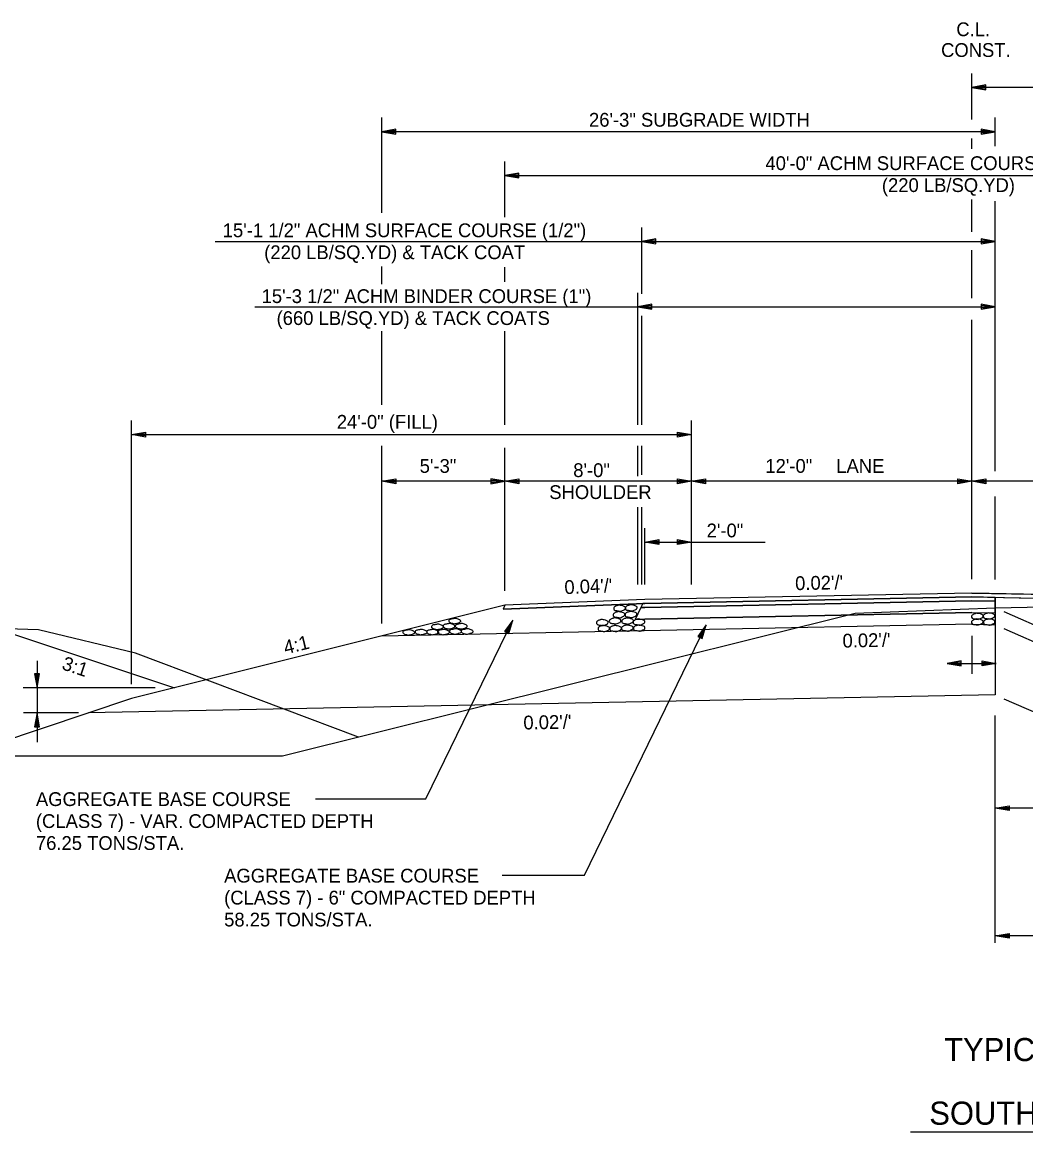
# Model space of a CAD drawing. Extents: x 1398565 to 1398920, y 1968324 to 1968581.
# Drawn here: x 1398600.91 to 1398643.9, y 1968376.33 to 1968423.84 of the extents above; entities that cross this region are included whole.
import ezdxf

# ---------------------------------------------------------------- set-up
doc = ezdxf.new("R2010")
doc.units = 0
for name, color, linetype in [('1', 7, 'Continuous'), ('10', 7, 'Continuous'), ('19', 7, 'Continuous'), ('42', 7, 'Continuous'), ('7', 7, 'Continuous'), ('Default', 7, 'Continuous'), ('Level 1', 7, 'Continuous')]:
    doc.layers.add(name, color=color, linetype=linetype)

# ---------------------------------------------------------------- blocks, each defined once
blk = doc.blocks.new('ROCKS')
at = {"layer": '1'}
blk.add_spline([(0.013, 0.06), (0.053, 0.053), (0.107, 0.033), (0.133, 0.013), (0.133, -0.007), (0.12, -0.033), (0.107, -0.04), (0.073, -0.053), (0.033, -0.067), (0.013, -0.067), (-0.02, -0.06), (-0.06, -0.053), (-0.087, -0.047), (-0.113, -0.02), (-0.113, -0.007), (-0.107, 0.02), (-0.087, 0.033), (-0.067, 0.047), (-0.033, 0.053), (-0.02, 0.06), (0.013, 0.06)], degree=3, dxfattribs=at)
blk = doc.blocks.new('4TO1 ABC')
at = {"layer": '1', "xscale": 0.1312491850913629, "yscale": 0.1312491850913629, "rotation": 180}
for p in [(0.00175, -0.00875), (-0.03325, -0.0385), (-0.016625, -0.023625), (0, -0.0385), (0.018375, -0.023625), (0.034125, -0.04025), (0.051625, -0.025375), (0.06475, -0.04025), (0.098, -0.04025), (0.133, -0.041125)]:
    blk.add_blockref('ROCKS', p, dxfattribs=at)

msp = doc.modelspace()

# ---------------------------------------------------------------- linework, layer by layer
at = {"layer": '19'}
for p, q in [((1398642.186, 1968421.154), (1398641.586, 1968421.049)), ((1398653.586, 1968421.049), (1398641.586, 1968421.049)), ((1398641.586, 1968421.049), (1398642.186, 1968420.944)), ((1398642.186, 1968421.099), (1398641.746, 1968421.064)), ((1398641.746, 1968421.034), (1398642.186, 1968420.994)), ((1398642.186, 1968420.944), (1398642.186, 1968421.154)), ((1398616.308, 1968415.673), (1398616.308, 1968419.754)), ((1398642.586, 1968418.534), (1398642.586, 1968419.754)), ((1398616.908, 1968419.259), (1398616.308, 1968419.154)), ((1398642.586, 1968419.154), (1398616.308, 1968419.154)), ((1398616.308, 1968419.154), (1398616.908, 1968419.049)), ((1398616.908, 1968419.204), (1398616.468, 1968419.169)), ((1398616.468, 1968419.139), (1398616.908, 1968419.099)), ((1398616.908, 1968419.049), (1398616.908, 1968419.259)), ((1398641.986, 1968419.26), (1398641.986, 1968419.05)), ((1398642.586, 1968419.154), (1398641.986, 1968419.26)), ((1398642.426, 1968419.169), (1398641.986, 1968419.205)), ((1398641.986, 1968419.05), (1398642.586, 1968419.154)), ((1398641.986, 1968419.1), (1398642.426, 1968419.139)), ((1398621.586, 1968415.492), (1398621.586, 1968417.879)), ((1398622.186, 1968417.384), (1398621.586, 1968417.279)), ((1398621.586, 1968417.279), (1398661.586, 1968417.279)), ((1398621.586, 1968417.279), (1398622.186, 1968417.174)), ((1398622.186, 1968417.329), (1398621.746, 1968417.294)), ((1398621.746, 1968417.264), (1398622.186, 1968417.224)), ((1398622.186, 1968417.174), (1398622.186, 1968417.384)), ((1398642.586, 1968404.617), (1398642.586, 1968416.185)), ((1398627.458, 1968412.208), (1398627.458, 1968415.057)), ((1398609.178, 1968414.457), (1398642.586, 1968414.457)), ((1398628.058, 1968414.562), (1398627.458, 1968414.457)), ((1398627.458, 1968414.457), (1398628.058, 1968414.352)), ((1398628.058, 1968414.507), (1398627.618, 1968414.472)), ((1398627.618, 1968414.442), (1398628.058, 1968414.402)), ((1398628.058, 1968414.352), (1398628.058, 1968414.562)), ((1398641.986, 1968414.562), (1398641.986, 1968414.352)), ((1398642.586, 1968414.457), (1398641.986, 1968414.562)), ((1398642.426, 1968414.472), (1398641.986, 1968414.507)), ((1398641.986, 1968414.352), (1398642.586, 1968414.457)), ((1398641.986, 1968414.402), (1398642.426, 1968414.442)), ((1398616.308, 1968412.63), (1398616.308, 1968413.383)), ((1398621.586, 1968412.72), (1398621.586, 1968413.353)), ((1398627.288, 1968406.601), (1398627.288, 1968412.259)), ((1398610.878, 1968411.659), (1398642.586, 1968411.659)), ((1398627.888, 1968411.764), (1398627.288, 1968411.659)), ((1398627.288, 1968411.659), (1398627.888, 1968411.554)), ((1398627.888, 1968411.709), (1398627.448, 1968411.674)), ((1398627.448, 1968411.644), (1398627.888, 1968411.604)), ((1398627.888, 1968411.554), (1398627.888, 1968411.764)), ((1398641.986, 1968411.765), (1398641.986, 1968411.555)), ((1398642.586, 1968411.659), (1398641.986, 1968411.765)), ((1398642.426, 1968411.674), (1398641.986, 1968411.71)), ((1398641.986, 1968411.555), (1398642.586, 1968411.659)), ((1398641.986, 1968411.605), (1398642.426, 1968411.644)), ((1398627.458, 1968406.601), (1398627.458, 1968411.274)), ((1398616.308, 1968407.46), (1398616.308, 1968410.612)), ((1398621.586, 1968406.601), (1398621.586, 1968410.612)), ((1398605.586, 1968395.496), (1398605.586, 1968406.783)), ((1398629.586, 1968399.76), (1398629.586, 1968406.783)), ((1398605.586, 1968406.183), (1398606.186, 1968406.288)), ((1398605.586, 1968406.183), (1398629.586, 1968406.183)), ((1398606.186, 1968406.078), (1398605.586, 1968406.183)), ((1398605.746, 1968406.198), (1398606.186, 1968406.233)), ((1398606.186, 1968406.128), (1398605.746, 1968406.168)), ((1398606.186, 1968406.288), (1398606.186, 1968406.078)), ((1398628.986, 1968406.078), (1398628.986, 1968406.288)), ((1398628.986, 1968406.288), (1398629.586, 1968406.183)), ((1398628.986, 1968406.233), (1398629.426, 1968406.198)), ((1398629.586, 1968406.183), (1398628.986, 1968406.078)), ((1398629.426, 1968406.168), (1398628.986, 1968406.128)), ((1398616.308, 1968398.1), (1398616.308, 1968405.701)), ((1398621.586, 1968399.498), (1398621.586, 1968405.611)), ((1398627.288, 1968404.406), (1398627.288, 1968405.701)), ((1398627.458, 1968404.466), (1398627.458, 1968405.701)), ((1398616.308, 1968404.184), (1398616.908, 1968404.289)), ((1398641.586, 1968404.184), (1398616.308, 1968404.184)), ((1398616.908, 1968404.079), (1398616.308, 1968404.184)), ((1398616.468, 1968404.199), (1398616.908, 1968404.234)), ((1398616.908, 1968404.289), (1398616.908, 1968404.079)), ((1398620.986, 1968404.289), (1398620.986, 1968404.079)), ((1398621.586, 1968404.184), (1398620.986, 1968404.289)), ((1398621.426, 1968404.199), (1398620.986, 1968404.234)), ((1398620.986, 1968404.079), (1398621.586, 1968404.184)), ((1398621.586, 1968404.184), (1398622.186, 1968404.289)), ((1398622.186, 1968404.079), (1398621.586, 1968404.184)), ((1398621.746, 1968404.199), (1398622.186, 1968404.234)), ((1398622.186, 1968404.289), (1398622.186, 1968404.079)), ((1398628.986, 1968404.079), (1398628.986, 1968404.289)), ((1398628.986, 1968404.289), (1398629.586, 1968404.184)), ((1398628.986, 1968404.234), (1398629.426, 1968404.199)), ((1398629.586, 1968404.184), (1398628.986, 1968404.079)), ((1398629.586, 1968404.184), (1398630.186, 1968404.289)), ((1398630.186, 1968404.079), (1398629.586, 1968404.184)), ((1398629.746, 1968404.199), (1398630.186, 1968404.234)), ((1398630.186, 1968404.289), (1398630.186, 1968404.079)), ((1398640.986, 1968404.079), (1398640.986, 1968404.289)), ((1398640.986, 1968404.289), (1398641.586, 1968404.184)), ((1398640.986, 1968404.234), (1398641.426, 1968404.199)), ((1398641.586, 1968404.184), (1398640.986, 1968404.079)), ((1398641.586, 1968404.184), (1398642.186, 1968404.289)), ((1398661.586, 1968404.184), (1398641.586, 1968404.184)), ((1398642.186, 1968404.079), (1398641.586, 1968404.184)), ((1398641.746, 1968404.199), (1398642.186, 1968404.234)), ((1398642.186, 1968404.289), (1398642.186, 1968404.079)), ((1398616.908, 1968404.129), (1398616.468, 1968404.169)), ((1398620.986, 1968404.129), (1398621.426, 1968404.169)), ((1398622.186, 1968404.129), (1398621.746, 1968404.169)), ((1398629.426, 1968404.169), (1398628.986, 1968404.129)), ((1398630.186, 1968404.129), (1398629.746, 1968404.169)), ((1398641.426, 1968404.169), (1398640.986, 1968404.129)), ((1398642.186, 1968404.129), (1398641.746, 1968404.169)), ((1398642.586, 1968399.98), (1398642.586, 1968403.532)), ((1398627.288, 1968399.76), (1398627.288, 1968403.081)), ((1398627.458, 1968399.76), (1398627.458, 1968403.081)), ((1398627.586, 1968399.76), (1398627.586, 1968402.182)), ((1398627.586, 1968401.582), (1398628.186, 1968401.687)), ((1398627.586, 1968401.582), (1398632.733, 1968401.582)), ((1398628.186, 1968401.477), (1398627.586, 1968401.582)), ((1398627.746, 1968401.597), (1398628.186, 1968401.632)), ((1398628.186, 1968401.527), (1398627.746, 1968401.567)), ((1398628.186, 1968401.687), (1398628.186, 1968401.477)), ((1398628.986, 1968401.477), (1398628.986, 1968401.687)), ((1398628.986, 1968401.687), (1398629.586, 1968401.582)), ((1398628.986, 1968401.632), (1398629.426, 1968401.597)), ((1398629.586, 1968401.582), (1398628.986, 1968401.477)), ((1398629.426, 1968401.567), (1398628.986, 1968401.527)), ((1398627.586, 1968399.12), (1398621.591, 1968398.881)), ((1398641.586, 1968399.4), (1398627.586, 1968399.12)), ((1398641.586, 1968399.234), (1398627.586, 1968398.954)), ((1398641.586, 1968399.067), (1398627.586, 1968398.787)), ((1398641.586, 1968399.4), (1398655.586, 1968399.12)), ((1398641.586, 1968399.234), (1398655.586, 1968398.954)), ((1398641.586, 1968399.067), (1398642.586, 1968399.047)), ((1398642.586, 1968399.047), (1398641.586, 1968399.067)), ((1398642.586, 1968399.214), (1398642.586, 1968397.755)), ((1398642.586, 1968398.547), (1398642.586, 1968399.047)), ((1398621.591, 1968398.881), (1398605.586, 1968394.879)), ((1398627.586, 1968398.954), (1398621.506, 1968398.71)), ((1398621.591, 1968398.881), (1398621.506, 1968398.71)), ((1398627.416, 1968398.78), (1398627.161, 1968398.27)), ((1398627.416, 1968398.78), (1398627.161, 1968398.27)), ((1398627.501, 1968398.95), (1398627.416, 1968398.78)), ((1398627.586, 1968398.787), (1398627.416, 1968398.78)), ((1398641.586, 1968398.567), (1398627.586, 1968398.287)), ((1398641.586, 1968398.567), (1398642.586, 1968398.547)), ((1398641.586, 1968398.567), (1398642.586, 1968398.547)), ((1398642.967, 1968398.606), (1398645.71, 1968397.396)), ((1398641.586, 1968398.065), (1398616.308, 1968397.559)), ((1398618.199, 1968390.586), (1398621.927, 1968398.244)), ((1398621.927, 1968398.244), (1398621.563, 1968397.755)), ((1398621.844, 1968398.107), (1398621.612, 1968397.734)), ((1398621.706, 1968397.685), (1398621.869, 1968398.094)), ((1398621.75, 1968397.663), (1398621.927, 1968398.244)), ((1398624.998, 1968387.326), (1398630.21, 1968398.033)), ((1398627.586, 1968398.287), (1398627.161, 1968398.27)), ((1398630.21, 1968398.033), (1398629.846, 1968397.544)), ((1398630.033, 1968397.451), (1398630.21, 1968398.033)), ((1398641.586, 1968398.065), (1398642.586, 1968398.045)), ((1398599.796, 1968397.888), (1398607.436, 1968395.342)), ((1398621.563, 1968397.755), (1398621.75, 1968397.663)), ((1398629.846, 1968397.544), (1398630.033, 1968397.451)), ((1398630.127, 1968397.896), (1398629.895, 1968397.523)), ((1398629.989, 1968397.474), (1398630.152, 1968397.883)), ((1398642.586, 1968397.755), (1398642.586, 1968395.045)), ((1398642.967, 1968397.877), (1398645.71, 1968396.667)), ((1398601.544, 1968396.499), (1398601.544, 1968395.224)), ((1398601.649, 1968395.942), (1398601.439, 1968395.942)), ((1398601.439, 1968395.942), (1398601.544, 1968395.342)), ((1398601.494, 1968395.942), (1398601.529, 1968395.502)), ((1398601.544, 1968395.342), (1398601.649, 1968395.942)), ((1398601.559, 1968395.502), (1398601.599, 1968395.942)), ((1398601.544, 1968395.224), (1398601.544, 1968393.018)), ((1398605.586, 1968394.879), (1398598.222, 1968392.424)), ((1398642.586, 1968395.045), (1398603.752, 1968394.268)), ((1398642.967, 1968394.877), (1398645.71, 1968393.667)), ((1398601.544, 1968394.268), (1398601.439, 1968393.668)), ((1398601.649, 1968393.668), (1398601.544, 1968394.268)), ((1398601.529, 1968394.108), (1398601.494, 1968393.668)), ((1398601.599, 1968393.668), (1398601.559, 1968394.108)), ((1398642.586, 1968384.418), (1398642.586, 1968394.155)), ((1398601.439, 1968393.668), (1398601.649, 1968393.668)), ((1398613.47, 1968390.586), (1398618.199, 1968390.586)), ((1398642.586, 1968390.189), (1398643.186, 1968390.294)), ((1398643.186, 1968390.084), (1398642.586, 1968390.189)), ((1398661.586, 1968390.189), (1398642.586, 1968390.189)), ((1398642.746, 1968390.204), (1398643.186, 1968390.239)), ((1398643.186, 1968390.134), (1398642.746, 1968390.174)), ((1398643.186, 1968390.294), (1398643.186, 1968390.084)), ((1398621.47, 1968387.326), (1398624.998, 1968387.326)), ((1398642.586, 1968384.725), (1398643.186, 1968384.83)), ((1398664.586, 1968384.725), (1398642.586, 1968384.725)), ((1398643.186, 1968384.62), (1398642.586, 1968384.725)), ((1398642.746, 1968384.74), (1398643.186, 1968384.775)), ((1398643.186, 1968384.67), (1398642.746, 1968384.71)), ((1398643.186, 1968384.83), (1398643.186, 1968384.62)), ((1398638.967, 1968376.334), (1398667.947, 1968376.334))]:
    msp.add_line(p, q, dxfattribs=at)
for points in [[(1398621.506, 1968398.71), (1398627.586, 1968398.954), (1398641.586, 1968399.234), (1398655.586, 1968398.954), (1398661.671, 1968398.71), (1398661.586, 1968398.88), (1398655.586, 1968399.12), (1398641.586, 1968399.4), (1398627.586, 1968399.12), (1398621.591, 1968398.881)], [(1398627.501, 1968398.95), (1398627.416, 1968398.78), (1398627.586, 1968398.787), (1398627.586, 1968398.787), (1398641.586, 1968399.067), (1398642.586, 1968399.047), (1398642.586, 1968399.214), (1398641.586, 1968399.234), (1398627.586, 1968398.954)]]:
    msp.add_lwpolyline(points, close=True, dxfattribs=at)
for points in [[(1398641.586, 1968399.067), (1398627.586, 1968398.787), (1398627.416, 1968398.78)], [(1398627.161, 1968398.27), (1398627.586, 1968398.287), (1398641.586, 1968398.567)]]:
    msp.add_lwpolyline(points, dxfattribs=at)
at = {"layer": '42'}
for p, q in [((1398641.586, 1968397.567), (1398641.586, 1968395.935)), ((1398641.138, 1968396.491), (1398640.538, 1968396.387)), ((1398640.538, 1968396.387), (1398641.138, 1968396.281)), ((1398640.538, 1968396.387), (1398642.634, 1968396.387)), ((1398641.138, 1968396.436), (1398640.698, 1968396.401)), ((1398640.698, 1968396.371), (1398641.138, 1968396.331)), ((1398641.138, 1968396.281), (1398641.138, 1968396.491)), ((1398642.034, 1968396.281), (1398642.034, 1968396.491)), ((1398642.034, 1968396.491), (1398642.634, 1968396.387)), ((1398642.034, 1968396.436), (1398642.474, 1968396.401)), ((1398642.634, 1968396.387), (1398642.034, 1968396.281)), ((1398642.474, 1968396.371), (1398642.034, 1968396.331))]:
    msp.add_line(p, q, dxfattribs=at)
for points in [[(1398642.586, 1968398.774), (1398653.586, 1968398.994)], [(1398565.563, 1968392.424), (1398612.06, 1968392.424), (1398636.586, 1968398.534), (1398642.586, 1968398.774)], [(1398615.319, 1968393.236), (1398605.766, 1968396.82), (1398601.609, 1968397.832), (1398593.902, 1968398.071), (1398586.821, 1968398.502), (1398577.688, 1968398.831), (1398565.772, 1968398.786)]]:
    msp.add_lwpolyline(points, dxfattribs=at)
at = {"layer": '7'}
for p, q in [((1398641.586, 1968419.679), (1398641.586, 1968421.649)), ((1398641.586, 1968418.414), (1398641.586, 1968418.866)), ((1398641.586, 1968414.859), (1398641.586, 1968416.245)), ((1398641.586, 1968412.028), (1398641.586, 1968414.076)), ((1398641.586, 1968400), (1398641.586, 1968411.094))]:
    msp.add_line(p, q, dxfattribs=at)
at = {"layer": 'Default'}
for p, q in [((1398606.603, 1968395.342), (1398600.949, 1968395.342)), ((1398603.316, 1968394.268), (1398600.963, 1968394.268))]:
    msp.add_line(p, q, dxfattribs=at)

# ---------------------------------------------------------------- block references
at = {"layer": '19', "xscale": 14.999970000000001, "yscale": -14.999970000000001, "rotation": 180}
msp.add_blockref('4TO1 ABC', (1398619.448, 1968398.327), dxfattribs=at)
at = {"layer": 'Level 1', "xscale": 2.011654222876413, "yscale": 2.011654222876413, "rotation": 1.8263814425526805}
for p in [(1398626.454, 1968398.478), (1398626.481, 1968398.757), (1398626.966, 1968398.489), (1398626.98, 1968398.772), (1398641.807, 1968398.409), (1398642.305, 1968398.424), (1398625.743, 1968398.142), (1398625.803, 1968397.887), (1398626.287, 1968398.212), (1398626.307, 1968397.886), (1398626.813, 1968397.907), (1398626.82, 1968398.208), (1398627.311, 1968398.164), (1398627.317, 1968397.906), (1398641.807, 1968398.167), (1398642.311, 1968398.166)]:
    msp.add_blockref('ROCKS', p, dxfattribs=at)

# ---------------------------------------------------------------- texts
at = {"layer": '10'}
for s, height, rotation, p in [('24\'-0" (FILL)', 0.59001, 360, (1398614.385, 1968406.435)), ('5\'-3"', 0.59, 0, (1398617.936, 1968404.547)), ('12\'-0" ', 0.59, 360, (1398632.744, 1968404.547)), ('LANE', 0.59, 360, (1398635.782, 1968404.547)), ('8\'-0" ', 0.59, 360, (1398624.515, 1968404.366)), ('SHOULDER', 0.59, 360, (1398623.488, 1968403.426)), ('2\'-0"', 0.59, 360, (1398630.229, 1968401.785)), ('4:1', 0.59, 13.7364, (1398612.189, 1968396.771)), ('3:1', 0.59, 341.5224, (1398602.569, 1968396.146))]:
    msp.add_text(s, height=height, rotation=rotation, dxfattribs=at).set_placement(p)
at = {"layer": '19'}
msp.add_text('C.L.', height=0.59, dxfattribs=at).set_placement((1398640.926, 1968423.242))
for s, height, rotation, p in [('CONST.', 0.59, 360, (1398640.273, 1968422.354)), ("0.04'/'", 0.59, 2.2906, (1398624.147, 1968399.352)), ("0.02'/'", 0.59, 1.1458, (1398634.025, 1968399.524)), ("0.02'/'", 0.59, 1.1458, (1398636.055, 1968397.062)), ("0.02'/'", 0.59, 1.1458, (1398622.384, 1968393.557)), ('AGGREGATE BASE COURSE', 0.59001, 360, (1398601.496, 1968390.282)), ('(CLASS 7) - VAR. COMPACTED DEPTH', 0.59001, 360, (1398601.496, 1968389.342)), ('76.25 TONS/STA.', 0.59001, 360, (1398601.496, 1968388.402)), ('AGGREGATE BASE COURSE', 0.59001, 360, (1398609.56, 1968387.005)), ('(CLASS 7) - 6" COMPACTED DEPTH', 0.59001, 360, (1398609.56, 1968386.065)), ('58.25 TONS/STA.', 0.59001, 360, (1398609.56, 1968385.125)), ('TYPICAL SECTION OF IMPROVEMENT', 0.98999, 360, (1398640.404, 1968379.36)), ('SOUTHBOUND PASSING LANE (SITE 2)', 0.98999, 360, (1398639.769, 1968376.637))]:
    msp.add_text(s, height=height, rotation=rotation, dxfattribs=at).set_placement(p)
at = {"layer": '42'}
for s, p in [('26\'-3" SUBGRADE WIDTH', (1398625.189, 1968419.367)), ('40\'-0" ACHM SURFACE COURSE (1/2")', (1398632.748, 1968417.51)), ('(220 LB/SQ.YD)', (1398637.737, 1968416.57)), ('15\'-1 1/2" ACHM SURFACE COURSE (1/2")', (1398609.499, 1968414.636)), ('(220 LB/SQ.YD) & TACK COAT', (1398611.276, 1968413.696)), ('15\'-3 1/2" ACHM BINDER COURSE (1")', (1398611.165, 1968411.817)), ('(660 LB/SQ.YD) & TACK COATS', (1398611.806, 1968410.877))]:
    msp.add_text(s, height=0.59001, rotation=360, dxfattribs=at).set_placement(p)

doc.saveas('drawing.dxf')
